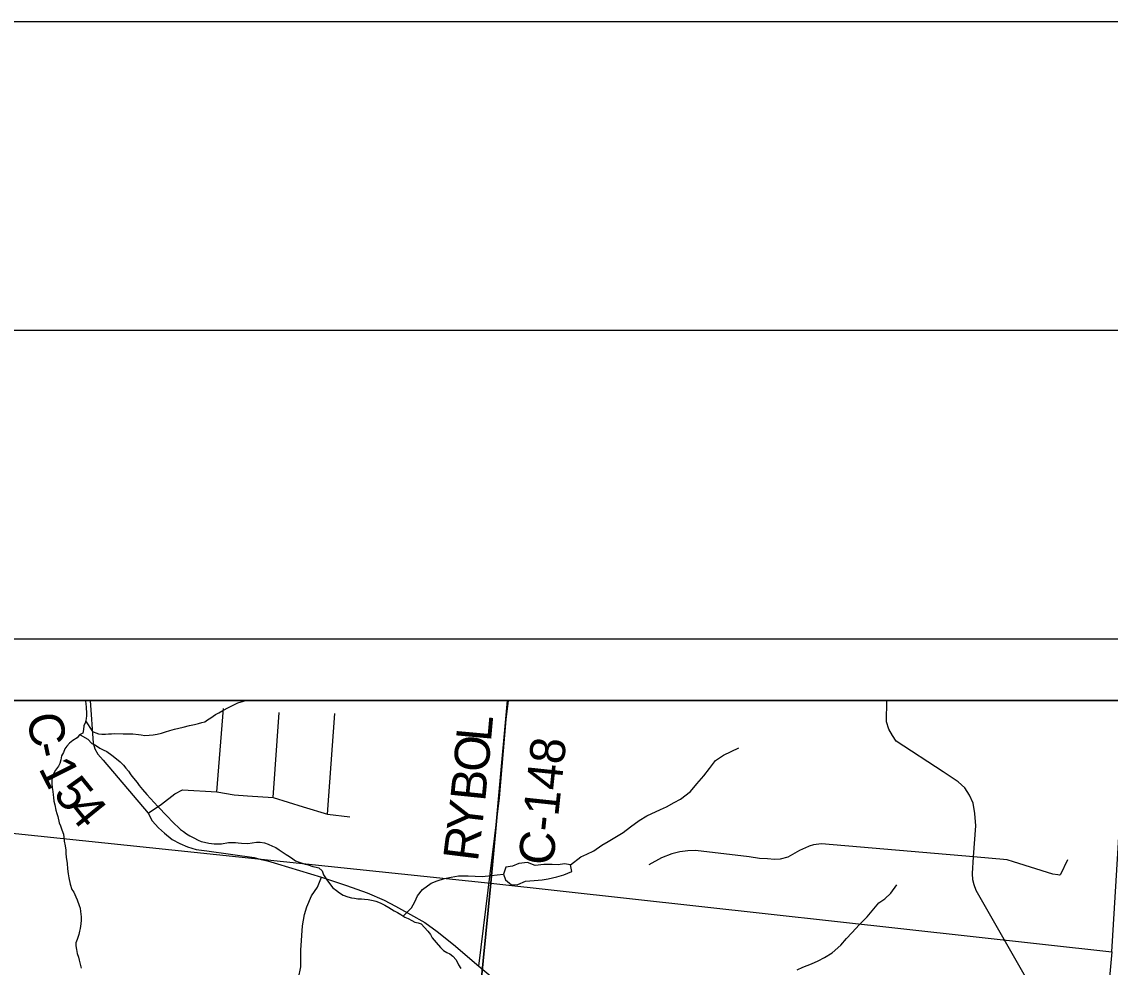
# Model space of a CAD drawing. Extents: x 0 to 43.4, y -8.1 to 22.
# Drawn here: x 4.286 to 6.05, y 20.468 to 22 of the extents above; entities that cross this region are included whole.
import ezdxf

# ---------------------------------------------------------------- set-up
doc = ezdxf.new("R2010")
doc.units = 0
for name, color, linetype in [('GM_X_Corporation', 7, 'Continuous'), ('GM_X_County_Road', 7, 'Continuous'), ('GM_X_County_Road_Text', 7, 'Continuous'), ('GM_X_Minor_Lake', 7, 'Continuous'), ('GM_X_Minor_River', 7, 'Continuous'), ('GM_X_Township_Road', 7, 'Continuous'), ('SH_Border', 7, 'Continuous'), ('SH_Cut_Line', 7, 'Continuous'), ('SH_Data', 7, 'Continuous')]:
    doc.layers.add(name, color=color, linetype=linetype)

msp = doc.modelspace()

# ---------------------------------------------------------------- linework, layer by layer
at = {"layer": 'GM_X_Corporation'}
for points in [[(8.9, 14.3814), (8.9, 20.9), (2.1, 20.9)], [(8.9, 17.1765), (8.9, 20.9), (4.0645, 20.9)]]:
    msp.add_lwpolyline(points, dxfattribs=at)
for points in [[(5.0731, 20.9), (4.0674, 20.9), (4.0476, 20.7082), (5.0456, 20.604)], [(6.077, 20.9), (5.0731, 20.9), (5.0456, 20.604), (6.0521, 20.4929)], [(4.0476, 20.7082), (5.0456, 20.604), (4.9462, 19.5972), (3.9403, 19.703)], [(6.0521, 20.4929), (5.9616, 19.4927), (4.9462, 19.5972), (5.0456, 20.604)]]:
    msp.add_lwpolyline(points, close=True, dxfattribs=at)
at = {"layer": 'GM_X_County_Road'}
for points in [[(4.3962, 20.9), (4.4014, 20.8308), (4.4042, 20.8216), (4.4089, 20.8132), (4.4177, 20.8031), (4.4907, 20.7173), (4.4967, 20.7049), (4.5074, 20.6936), (4.517, 20.685), (4.5292, 20.6748), (4.542, 20.6683), (4.554, 20.6631), (4.5683, 20.6585), (4.5853, 20.6562), (4.6625, 20.6454), (4.6738, 20.6425), (4.6839, 20.6403), (4.7001, 20.6353), (4.7713, 20.6137)], [(5.0263, 20.4697), (5.0598, 20.7421), (5.0709, 20.8694), (5.0742, 20.9)], [(6.0357, 20.3327), (5.9847, 20.3361), (5.9794, 20.3381), (5.975, 20.3428), (5.8326, 20.592), (5.8291, 20.6012), (5.8268, 20.6093), (5.8263, 20.6196), (5.8283, 20.6466), (5.8319, 20.6972), (5.8303, 20.7167), (5.8274, 20.7335), (5.8218, 20.7469), (5.8142, 20.7586), (5.8035, 20.7684), (5.779, 20.7844), (5.7029, 20.8343), (5.6968, 20.8432), (5.6908, 20.8537), (5.6869, 20.8655), (5.6878, 20.9)], [(4.7342, 20.4502), (4.7377, 20.4687), (4.7381, 20.4953), (4.7407, 20.5347), (4.7438, 20.5532), (4.7476, 20.5657), (4.7553, 20.5833), (4.7648, 20.5975), (4.7713, 20.6137)], [(4.7713, 20.6137), (4.8119, 20.6005), (4.8454, 20.5882), (4.8732, 20.5764), (4.8915, 20.5665), (4.9154, 20.5533), (4.939, 20.5401), (4.9587, 20.5256), (4.9851, 20.5047), (5.0263, 20.4697)], [(5.0263, 20.4697), (5.0396, 20.4585), (5.092, 20.4145), (5.1031, 20.4047), (5.1132, 20.3988), (5.1282, 20.3934), (5.2144, 20.3532), (5.2275, 20.3464), (5.2368, 20.3393), (5.2531, 20.3229), (5.3235, 20.2455), (5.3348, 20.2308), (5.3873, 20.1625), (5.3964, 20.1497), (5.4053, 20.1411), (5.4206, 20.1323), (5.4859, 20.0972)]]:
    msp.add_lwpolyline(points, dxfattribs=at)
at = {"layer": 'GM_X_Minor_Lake'}
for points in [[(5.1179, 20.6324), (5.1055, 20.6373), (5.091, 20.6357), (5.0811, 20.6318), (5.07, 20.6298), (5.0663, 20.6184)], [(5.0663, 20.6186), (5.0694, 20.6093), (5.0795, 20.6011), (5.0894, 20.602), (5.1021, 20.607), (5.1158, 20.6085), (5.1291, 20.6093), (5.1386, 20.6109), (5.1528, 20.6144), (5.1643, 20.6175), (5.177, 20.6232), (5.175, 20.6339), (5.1651, 20.6353), (5.1552, 20.6337), (5.1453, 20.6343), (5.1317, 20.6343), (5.1179, 20.6324)]]:
    msp.add_lwpolyline(points, dxfattribs=at)
at = {"layer": 'GM_X_Minor_River'}
for points in [[(4.3884, 20.9), (4.3892, 20.8956), (4.39, 20.8883), (4.3905, 20.8803), (4.3904, 20.8758), (4.3898, 20.8701), (4.3881, 20.8641), (4.3864, 20.8592), (4.3854, 20.8528), (4.3848, 20.8471), (4.3794, 20.8442), (4.3751, 20.8394), (4.3685, 20.8355), (4.363, 20.8307), (4.3587, 20.8263), (4.3551, 20.8215), (4.353, 20.8159), (4.3502, 20.8103), (4.3488, 20.8039), (4.3471, 20.7982), (4.345, 20.7934), (4.3402, 20.7871), (4.3374, 20.7822), (4.3354, 20.7774), (4.3344, 20.7709), (4.3342, 20.7652), (4.3347, 20.7588), (4.336, 20.7526), (4.3366, 20.7473), (4.3372, 20.7427), (4.3378, 20.737), (4.3391, 20.7312), (4.341, 20.7221), (4.3424, 20.7167), (4.3441, 20.7121), (4.346, 20.7017), (4.3485, 20.6967), (4.3506, 20.6906), (4.353, 20.6836), (4.354, 20.6787), (4.3545, 20.6722), (4.3558, 20.6646), (4.357, 20.6577), (4.3572, 20.652), (4.3578, 20.6459), (4.359, 20.6359), (4.3598, 20.6272), (4.361, 20.6191), (4.3619, 20.6127), (4.3642, 20.6023), (4.3666, 20.5939), (4.3699, 20.5892), (4.373, 20.5819), (4.3752, 20.5772), (4.3786, 20.568), (4.38, 20.5634), (4.3809, 20.558), (4.3818, 20.5493), (4.382, 20.5439), (4.3814, 20.5383), (4.38, 20.5307), (4.3791, 20.5262), (4.3778, 20.5209), (4.3752, 20.513), (4.3731, 20.5074), (4.3733, 20.5024), (4.3743, 20.4967), (4.3752, 20.4902), (4.3776, 20.484), (4.3786, 20.4791), (4.3803, 20.4725), (4.382, 20.4664)], [(4.3889, 20.8669), (4.4001, 20.8496), (4.4054, 20.8479), (4.4102, 20.8462), (4.4155, 20.8457), (4.4212, 20.8455), (4.4262, 20.846), (4.4311, 20.8463), (4.4357, 20.8465), (4.4501, 20.846), (4.4554, 20.8462), (4.4657, 20.8458), (4.4747, 20.8447), (4.4793, 20.8442), (4.4849, 20.8436), (4.4918, 20.8438), (4.4986, 20.8443), (4.5048, 20.8456), (4.512, 20.8473), (4.5185, 20.8493), (4.5255, 20.8517), (4.5331, 20.8538), (4.5404, 20.8554), (4.5473, 20.8571), (4.5576, 20.8594), (4.5653, 20.861), (4.5722, 20.863), (4.5775, 20.8644), (4.5821, 20.8657), (4.5868, 20.8686), (4.5918, 20.8719), (4.5996, 20.8773), (4.6047, 20.8802), (4.6112, 20.8837), (4.6205, 20.8887), (4.6302, 20.8937), (4.636, 20.8962), (4.6448, 20.8989), (4.6482, 20.9)], [(4.38, 20.8445), (4.3928, 20.8373), (4.3994, 20.8302), (4.405, 20.8274), (4.4121, 20.823), (4.4177, 20.8201), (4.4237, 20.8172), (4.4314, 20.8117), (4.4392, 20.8057), (4.4451, 20.8005), (4.4506, 20.795), (4.4543, 20.7904), (4.4583, 20.7853), (4.4626, 20.7798), (4.4666, 20.7743), (4.4724, 20.7669), (4.4761, 20.7622), (4.4811, 20.7556), (4.4881, 20.7478), (4.506, 20.7285), (4.5104, 20.7242), (4.5167, 20.7171), (4.5233, 20.7104), (4.528, 20.705), (4.5335, 20.6995), (4.5383, 20.6951), (4.5431, 20.6911), (4.5475, 20.6876), (4.5527, 20.684), (4.5579, 20.6807), (4.5643, 20.6775), (4.5713, 20.6738), (4.5766, 20.6717), (4.5815, 20.6704), (4.589, 20.669), (4.5973, 20.6676), (4.6019, 20.6675), (4.6095, 20.6679), (4.6209, 20.6698), (4.6263, 20.67), (4.632, 20.6698), (4.6365, 20.6693), (4.6418, 20.6687), (4.652, 20.6684), (4.6589, 20.6693), (4.6658, 20.6706), (4.6722, 20.6703), (4.679, 20.6693), (4.685, 20.6672), (4.6917, 20.664), (4.6974, 20.6619), (4.7029, 20.6583), (4.714, 20.6503), (4.7193, 20.6471), (4.7248, 20.6434), (4.7293, 20.6403), (4.7349, 20.6382), (4.7401, 20.6365), (4.745, 20.6348), (4.7499, 20.6335), (4.7574, 20.6313), (4.7627, 20.63), (4.7672, 20.6287), (4.7724, 20.6239), (4.7748, 20.6174), (4.7802, 20.6096), (4.7842, 20.6034), (4.79, 20.5967), (4.7956, 20.592), (4.8004, 20.5884), (4.8063, 20.5848), (4.8138, 20.5818), (4.8202, 20.5801), (4.8248, 20.5796), (4.8304, 20.5786), (4.8361, 20.5784), (4.841, 20.5779), (4.8471, 20.5773), (4.855, 20.5759), (4.8595, 20.5746), (4.8666, 20.5724), (4.8741, 20.5684), (4.8804, 20.5647), (4.8893, 20.5591), (4.8946, 20.5563), (4.9001, 20.553), (4.9065, 20.549), (4.9121, 20.5465), (4.918, 20.5437), (4.9229, 20.5408), (4.9278, 20.5395), (4.933, 20.5382), (4.9385, 20.5323), (4.9437, 20.5264), (4.948, 20.5206), (4.9505, 20.5156), (4.9571, 20.5077), (4.9644, 20.4995), (4.9691, 20.4948), (4.9747, 20.4919), (4.9792, 20.4895)], [(5.175, 20.6339), (5.1919, 20.6465), (5.2015, 20.6511), (5.2127, 20.6565), (5.2255, 20.6657), (5.2359, 20.6718), (5.2494, 20.6794), (5.2602, 20.686), (5.2723, 20.6955), (5.2862, 20.7054), (5.2986, 20.7134), (5.3209, 20.7234), (5.3306, 20.7277), (5.3429, 20.7349), (5.3533, 20.7399), (5.3693, 20.7524), (5.3799, 20.765), (5.3913, 20.778), (5.4003, 20.7899), (5.4098, 20.8026), (5.423, 20.8113), (5.4353, 20.8174), (5.4476, 20.8232)], [(4.9039, 20.5506), (4.9172, 20.5638), (4.9224, 20.5736), (4.9272, 20.5833), (4.9351, 20.5937), (4.9491, 20.604), (4.9587, 20.6079), (4.9706, 20.6114), (4.9813, 20.6137), (4.9935, 20.616), (5.0091, 20.616), (5.0204, 20.6153), (5.0318, 20.6149), (5.0467, 20.6164), (5.0562, 20.6177), (5.0663, 20.6186)], [(5.5421, 20.4635), (5.5517, 20.4678), (5.5655, 20.4731), (5.5763, 20.4781), (5.5864, 20.4836), (5.5991, 20.4912), (5.6131, 20.5033), (5.6222, 20.5141), (5.6308, 20.5237), (5.6433, 20.5371), (5.6559, 20.5492), (5.6641, 20.5593), (5.6747, 20.5719), (5.6844, 20.5785), (5.6942, 20.5877), (5.7037, 20.6015)], [(4.9792, 20.4895), (4.9844, 20.4855), (4.9895, 20.4796), (4.9934, 20.4719), (4.9974, 20.4657)]]:
    msp.add_lwpolyline(points, dxfattribs=at)
at = {"layer": 'GM_X_Township_Road'}
for p, q in [((4.6018, 20.7522), (4.6126, 20.8873)), ((4.693, 20.743), (4.7025, 20.8805)), ((4.7809, 20.7159), (4.7929, 20.8789))]:
    msp.add_line(p, q, dxfattribs=at)
for points in [[(4.4907, 20.7173), (4.5119, 20.7321), (4.5335, 20.7488), (4.5463, 20.7554), (4.6018, 20.7522), (4.6296, 20.747), (4.6514, 20.7456), (4.693, 20.743), (4.7418, 20.728)], [(4.7418, 20.728), (4.7809, 20.7159), (4.8172, 20.7115)], [(5.5609, 20.6635), (5.5463, 20.6567), (5.527, 20.6461), (5.5148, 20.6431), (5.5054, 20.6424), (5.4945, 20.6434), (5.4813, 20.6442), (5.4645, 20.6466), (5.3778, 20.6567), (5.3653, 20.6563), (5.3519, 20.6546), (5.339, 20.6513), (5.3224, 20.6449), (5.302, 20.634)], [(5.9806, 20.6416), (5.9692, 20.618), (5.9685, 20.6175), (5.9675, 20.6172), (5.9646, 20.6174), (5.9567, 20.6188), (5.8929, 20.6387), (5.8828, 20.6417), (5.8283, 20.6466), (5.5816, 20.6678), (5.5687, 20.6662), (5.5618, 20.6639), (5.5609, 20.6635)]]:
    msp.add_lwpolyline(points, dxfattribs=at)
at = {"layer": 'SH_Border'}
msp.add_lwpolyline([(1.5, 21.5), (33.5, 21.5), (33.5, 0.5), (1.5, 0.5)], close=True, dxfattribs=at)
at = {"layer": 'SH_Cut_Line'}
msp.add_lwpolyline([(0, 0), (34, 0), (34, 22), (0, 22)], close=True, dxfattribs=at)
at = {"layer": 'SH_Data'}
for p, q in [((2, 21), (9, 21)), ((2.1, 20.9), (8.9, 20.9))]:
    msp.add_line(p, q, dxfattribs=at)

# ---------------------------------------------------------------- texts
at = {"layer": 'GM_X_County_Road_Text'}
for s, height, rotation, p in [('C', 0.0568, 280.28, (4.2934, 20.8753)), ('L', 0.0568, 84.8271, (5.0459, 20.8322)), ('O', 0.0568, 84.797, (5.0414, 20.7824)), ('C-148', 0.05682, 83.9636, (5.1466, 20.6313)), ('-', 0.0568, 282.0745, (4.3021, 20.8278)), ('1', 0.0568, 296.6444, (4.3121, 20.7904)), ('B', 0.0568, 84.1512, (5.0365, 20.7353)), ('5', 0.0568, 309.0137, (4.3349, 20.7481)), ('4', 0.0568, 309.0164, (4.3568, 20.7211)), ('Y', 0.0568, 83.1719, (5.0305, 20.6846)), ('R', 0.0568, 82.8755, (5.0247, 20.6379))]:
    msp.add_text(s, height=height, rotation=rotation, dxfattribs=at).set_placement(p)

doc.saveas('drawing.dxf')
